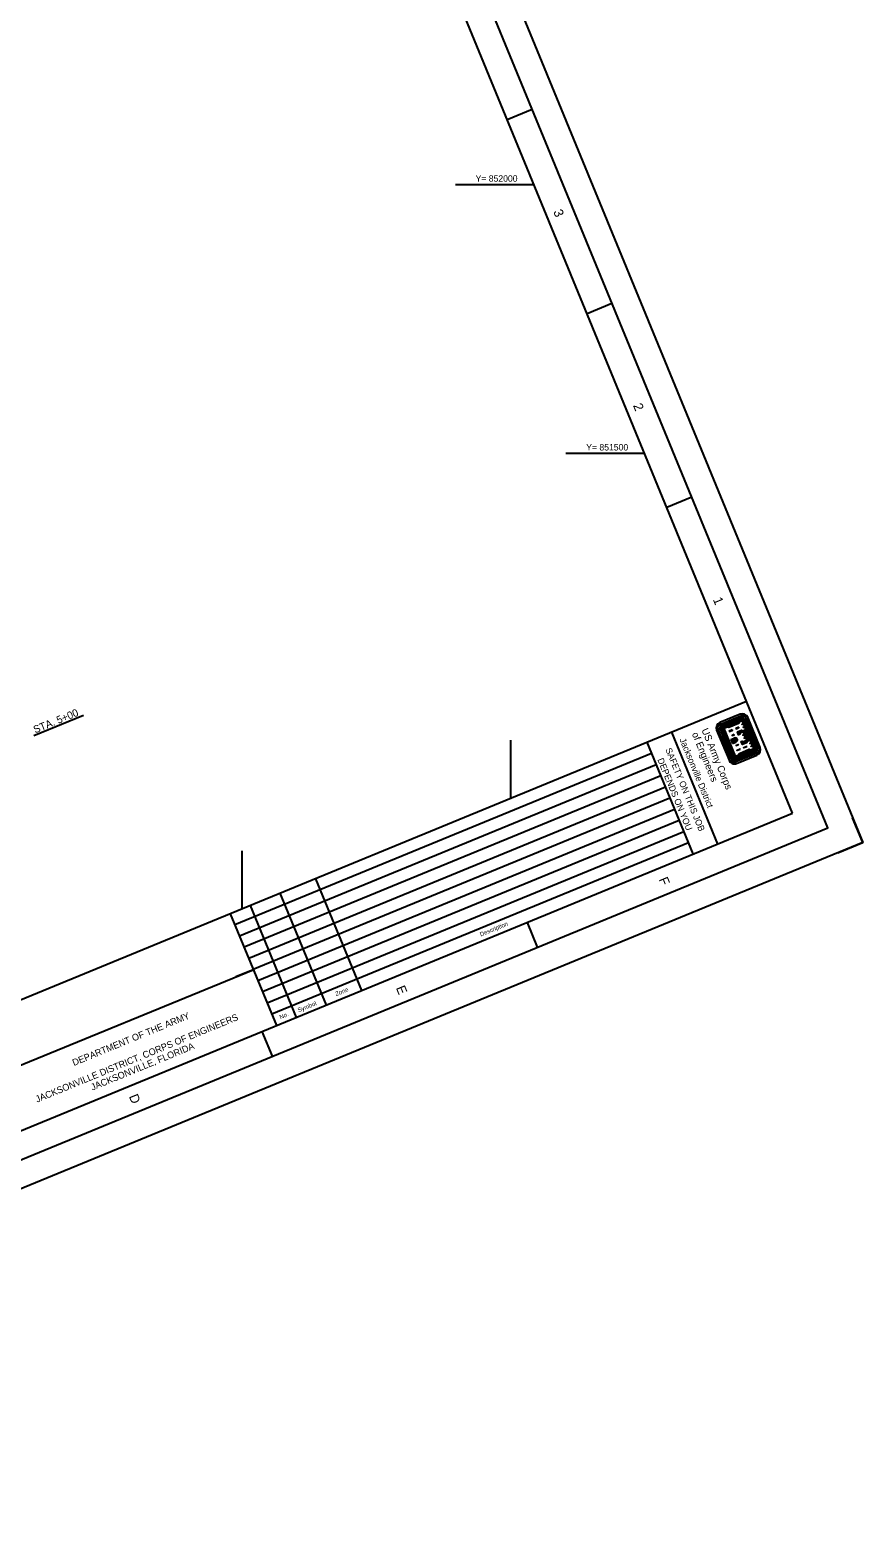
# Model space of a CAD drawing. Extents: x 580836 to 585655, y 849482 to 854845.
# Drawn here: x 584106 to 585655, y 849482 to 852287 of the extents above; entities that cross this region are included whole.
import ezdxf

# ---------------------------------------------------------------- set-up
doc = ezdxf.new("R2010")
doc.units = 0
for name, color, linetype in [('G-ANNO-NPLT', 7, 'Continuous'), ('G-ANNO-TEXT-LOGO', 7, 'Continuous'), ('G-ANNO-TEXT-TTLB', 7, 'Continuous'), ('G-ANNO-TTLB', 7, 'Continuous'), ('V-ALGN-TEXT', 7, 'Continuous'), ('V-TOPO-COOR-STAT', 7, 'Continuous')]:
    doc.layers.add(name, color=color, linetype=linetype)

msp = doc.modelspace()

# ---------------------------------------------------------------- linework, layer by layer
at = {"layer": 'G-ANNO-NPLT'}
msp.add_lwpolyline([(583980.5, 854844.8), (585654.5, 850775.7), (582510.3, 849482.1), (580836.2, 853551.2)], close=True, dxfattribs=at)
msp.add_lwpolyline([(585608.3, 850756.7), (585654.5, 850775.7), (585635.5, 850821.9)], dxfattribs=at)
at = {"layer": 'G-ANNO-TEXT-LOGO'}
for p, q in [((585426.4, 851014.5), (585388.5, 850998.9)), ((585382.6, 850984.9), (585405.7, 850928.7)), ((585408.8, 850929.9), (585385.7, 850986.2)), ((585412, 850931.3), (585388.9, 850987.5)), ((585412.8, 850931.6), (585389.6, 850987.8)), ((585389.7, 850995.9), (585427.6, 851011.5)), ((585413.6, 850931.9), (585390.5, 850988.1)), ((585429, 851008.3), (585391.1, 850992.7)), ((585414.4, 850932.3), (585391.3, 850988.5)), ((585429.3, 851007.5), (585391.4, 850991.9)), ((585429.6, 851006.7), (585391.7, 850991.1)), ((585415.2, 850932.6), (585392, 850988.8)), ((585430, 851005.9), (585392.1, 850990.3)), ((585430.3, 851005.1), (585392.4, 850989.5)), ((585430.7, 851004.2), (585393, 850988.8)), ((585415.8, 850933.3), (585393, 850988.8)), ((585431, 851003.5), (585394.2, 850988.4)), ((585416.4, 850934.3), (585394.2, 850988.4)), ((585423.2, 850999.5), (585403.8, 850991.6)), ((585422.7, 850998.4), (585405, 850991.1)), ((585454.2, 850948.6), (585431.1, 851004.8)), ((585455, 850949), (585431.9, 851005.2)), ((585455.8, 850949.3), (585432.6, 851005.5)), ((585456.6, 850949.6), (585433.5, 851005.8)), ((585457.4, 850949.9), (585434.3, 851006.2)), ((585437.4, 851007.5), (585460.6, 850951.2)), ((585438.3, 850985), (585445.4, 850967.8)), ((585463.5, 850952.5), (585440.4, 851008.7)), ((585409.2, 850967.3), (585415.4, 850969.8)), ((585409.2, 850967.3), (585412.2, 850959.9)), ((585409.5, 850966.6), (585415.7, 850969.1)), ((585409.8, 850965.7), (585416, 850968.3)), ((585410.2, 850964.9), (585416.4, 850967.4)), ((585410.5, 850964.2), (585416.7, 850966.7)), ((585410.9, 850963), (585417.1, 850965.6)), ((585411.3, 850962.3), (585417.4, 850964.9)), ((585411.6, 850961.5), (585417.8, 850964)), ((585411.9, 850960.6), (585418.1, 850963.2)), ((585412.2, 850959.9), (585418.4, 850962.4)), ((585433.5, 850983), (585440.6, 850965.8)), ((585434.4, 850983.4), (585441.4, 850966.2)), ((585435.1, 850983.7), (585442.2, 850966.5)), ((585435.9, 850984), (585443, 850966.8)), ((585436.8, 850984.4), (585443.8, 850967.2)), ((585437.5, 850984.7), (585444.6, 850967.5)), ((585453.5, 850948.8), (585415.8, 850933.3)), ((585453.8, 850947.9), (585415.9, 850932.3)), ((585454.2, 850947.1), (585416.3, 850931.5)), ((585453.2, 850949.5), (585416.4, 850934.3)), ((585454.5, 850946.3), (585416.6, 850930.7)), ((585454.8, 850945.5), (585416.9, 850929.9)), ((585455.2, 850944.7), (585417.2, 850929.1)), ((585456.5, 850941.5), (585418.5, 850925.9)), ((585419.8, 850922.9), (585457.7, 850938.5)), ((585444.8, 850946.8), (585425.5, 850938.9)), ((585443.7, 850947.3), (585426, 850940.1))]:
    msp.add_line(p, q, dxfattribs=at)
for points in [[(585431.2, 851002.9), (585423.9, 850999.8), (585423, 850997.6), (585405.3, 850990.4), (585403, 850991.2), (585395, 850987.9), (585416.7, 850935.2), (585424.7, 850938.5), (585425.7, 850940.9), (585443.3, 850948.2), (585445.6, 850947.1), (585452.9, 850950.1), (585450.1, 850957.1), (585447.9, 850962.4), (585445.8, 850967.4), (585438.5, 850964.4), (585437.6, 850962), (585431.2, 850959.4), (585429.6, 850963.2), (585430.2, 850963.5), (585432.6, 850962.5), (585439.8, 850965.5), (585436.9, 850972.4), (585434.7, 850977.8), (585432.7, 850982.7), (585425.5, 850979.7), (585424.5, 850977.4), (585423.9, 850977.1), (585422.3, 850981), (585428.7, 850983.7), (585431, 850982.6), (585438.3, 850985.7), (585435.4, 850992.6), (585433.2, 850998), (585431.2, 851002.9)], [(585430.7, 851001.8), (585424.6, 850999.3), (585423.6, 850996.9), (585405.3, 850989.4), (585403, 850990.4), (585396.1, 850987.5), (585417.2, 850936.3), (585424, 850939.1), (585425, 850941.6), (585443.3, 850949.1), (585445.7, 850948), (585451.8, 850950.5), (585449.7, 850955.5), (585446.9, 850954.4), (585446.7, 850954.8), (585449.5, 850956), (585447.5, 850960.9), (585444.6, 850959.7), (585444.5, 850960.1), (585447.4, 850961.3), (585445.3, 850966.3), (585439.2, 850963.7), (585438.2, 850961.4), (585430.7, 850958.3), (585428.5, 850963.7), (585430.3, 850964.4), (585432.6, 850963.4), (585438.7, 850965.9), (585436.7, 850970.9), (585433.8, 850969.7), (585433.7, 850970.1), (585436.5, 850971.3), (585434.5, 850976.3), (585431.6, 850975.1), (585431.4, 850975.6), (585434.3, 850976.8), (585432.3, 850981.7), (585426.2, 850979.1), (585425.2, 850976.8), (585423.4, 850976.1), (585421.2, 850981.4), (585428.7, 850984.5), (585431.1, 850983.5), (585437.2, 850986), (585435.1, 850991), (585432.3, 850989.8), (585432.1, 850990.2), (585435, 850991.4), (585432.9, 850996.4), (585430, 850995.2), (585429.9, 850995.6), (585432.8, 850996.8), (585430.7, 851001.8)], [(585411.6, 850985.1), (585406.2, 850982.8), (585406.4, 850982.3), (585411.9, 850984.5), (585411.6, 850985.1)], [(585423.9, 850990.1), (585418.6, 850987.9), (585418.8, 850987.4), (585424.2, 850989.6), (585423.9, 850990.1)], [(585415.1, 850976.5), (585411.3, 850975), (585411.5, 850974.5), (585415.3, 850976.1), (585415.1, 850976.5)], [(585423, 850957.5), (585419.2, 850955.9), (585419, 850956.4), (585422.8, 850958), (585423, 850957.5)], [(585429.4, 850982.4), (585428.7, 850982.7), (585423.4, 850980.5), (585424.2, 850978.8), (585424.9, 850980.5), (585429.5, 850982.4)], [(585437.2, 850963.4), (585436.9, 850962.7), (585431.7, 850960.5), (585431, 850962.2), (585432.6, 850961.6), (585437.3, 850963.5)], [(585426.4, 850949.1), (585421, 850946.8), (585420.8, 850947.3), (585426.2, 850949.5), (585426.4, 850949.1)], [(585438.7, 850954.1), (585433.4, 850951.9), (585433.2, 850952.4), (585438.5, 850954.6), (585438.7, 850954.1)]]:
    msp.add_lwpolyline(points, dxfattribs=at)
for centre, major_axis, start_param, end_param in [((585430.5, 851004.6), (4.08, -9.91), 1.57078, 3.141576), ((585430.5, 851004.6), (2.85, -6.93), 1.57078, 3.141576), ((585392.6, 850989), (-4.08, 9.91), 6.28317, 7.853966), ((585392.6, 850989), (-2.85, 6.93), 6.28317, 7.853966), ((585392.6, 850989), (-1.53, 3.72), 6.28317, 7.853966), ((585392.6, 850989), (-1.2, 2.91), 6.28317, 7.853966), ((585392.6, 850989), (-0.87, 2.11), 6.28317, 7.853966), ((585392.6, 850989), (-0.54, 1.31), 6.28317, 7.853966), ((585392.6, 850989), (-0.208, 0.505), 6.28317, 7.853966), ((585430.5, 851004.6), (1.53, -3.72), 1.57078, 3.141576), ((585430.5, 851004.6), (1.2, -2.91), 1.57078, 3.141576), ((585430.5, 851004.6), (0.87, -2.11), 1.57078, 3.141576), ((585430.5, 851004.6), (0.54, -1.31), 1.57078, 3.141576), ((585430.5, 851004.6), (0.208, -0.505), 1.57078, 3.141576), ((585417.1, 850964.6), (-2.11, 5.14), 4.985832, 6.214359), ((585417.1, 850964.6), (-1.78, 4.33), 4.947465, 6.21436), ((585417.1, 850964.6), (-1.45, 3.53), 4.947465, 6.21436), ((585417.1, 850964.6), (-1.12, 2.73), 4.947465, 6.21436), ((585417.1, 850964.6), (-0.79, 1.92), 4.947465, 6.214359), ((585415.9, 850967.4), (0.79, -1.92), 0.068794, 1.335689), ((585415.9, 850967.4), (1.12, -2.73), 0.068794, 1.335689), ((585415.9, 850967.4), (1.45, -3.53), 0.068795, 1.335689), ((585415.9, 850967.4), (1.78, -4.33), 0.068795, 1.335689), ((585415.9, 850967.4), (2.11, -5.14), 0.068795, 1.29842), ((585415.7, 850932.8), (4.08, -9.91), 4.712373, 6.28317), ((585415.7, 850932.8), (-2.85, 6.93), 1.570781, 3.141577), ((585415.7, 850932.8), (1.53, -3.72), 4.712373, 6.28317), ((585415.7, 850932.8), (1.2, -2.91), 4.712373, 6.28317), ((585415.7, 850932.8), (0.87, -2.11), 4.712373, 6.28317), ((585415.7, 850932.8), (0.54, -1.31), 4.712373, 6.28317), ((585415.7, 850932.8), (0.208, -0.505), 4.712373, 6.28317), ((585453.6, 850948.4), (0.208, -0.505), 6.283169, 7.853965), ((585453.6, 850948.4), (0.54, -1.31), 6.283169, 7.853965), ((585453.6, 850948.4), (0.87, -2.11), 6.283169, 7.853965), ((585453.6, 850948.4), (1.2, -2.91), 6.283169, 7.853965), ((585453.6, 850948.4), (1.53, -3.72), 6.283169, 7.853965), ((585453.6, 850948.4), (2.85, -6.93), 6.28317, 7.853966), ((585453.6, 850948.4), (4.08, -9.91), 6.283169, 7.853965)]:
    msp.add_ellipse(centre, major_axis=major_axis, ratio=0.99964, start_param=start_param, end_param=end_param, dxfattribs=at)
at = {"layer": 'G-ANNO-TTLB'}
for p, q in [((585039.5, 852139.2), (584993.3, 852120.2)), ((585187.9, 851778.6), (585141.6, 851759.5)), ((585336.3, 851417.9), (585290, 851398.9)), ((585438.4, 851038.2), (582479.1, 849820.7)), ((585252.9, 850962.5), (585338.5, 850754.5)), ((585298.5, 850980.7), (585384.2, 850772.6)), ((585261.6, 850941.3), (584486.7, 850622.5)), ((585270.2, 850920.5), (584495.3, 850601.7)), ((585278.7, 850899.7), (584503.8, 850580.9)), ((585287.3, 850878.9), (584512.4, 850560.1)), ((585295.8, 850858.1), (584521, 850539.3)), ((585304.4, 850837.3), (584529.5, 850518.5)), ((585313, 850816.5), (584538.1, 850497.7)), ((585321.5, 850795.7), (584546.6, 850476.9)), ((585330.1, 850774.9), (584555.2, 850456.1)), ((584636.4, 850708.2), (584722, 850500.2)), ((584570.6, 850681.2), (584656.2, 850473.1)), ((584515.1, 850658.3), (584600.6, 850450.2)), ((584478.2, 850643.2), (584563.8, 850435.1)), ((585049.7, 850580.9), (585030.6, 850627.1)), ((583725.9, 850212.7), (584521, 850539.1)), ((584521, 850539.1), (584488.3, 850525.7)), ((584556.5, 850378), (584537.4, 850424.2))]:
    msp.add_line(p, q, dxfattribs=at)
for points in [[(580901.5, 853523.9), (582537.5, 849547.4), (585589.3, 850802.9), (583953.2, 854779.5)], [(585524, 850830.1), (583954.6, 854644.9), (580995.3, 853427.4), (582564.7, 849612.6)]]:
    msp.add_lwpolyline(points, close=True, dxfattribs=at)
at = {"layer": 'V-ALGN-TEXT'}
msp.add_line((584113, 850974.5), (584205.4, 851012.6), dxfattribs=at)
at = {"layer": 'V-TOPO-COOR-STAT'}
for p, q in [((584896.7, 852000), (585042.7, 852000)), ((585102.4, 851500), (585248.4, 851500)), ((585000, 850857.9), (585000, 850966)), ((584500, 850652.2), (584500, 850760.3))]:
    msp.add_line(p, q, dxfattribs=at)

# ---------------------------------------------------------------- texts
at = {"layer": 'G-ANNO-TEXT-TTLB'}
for s, height, rotation, p in [('US Army Corps', 13.086, 292.363, (585354.2, 850985.2)), ('Jacksonville District', 11.9, 292.363, (585313.3, 850967.3)), ('of Engineers', 13.086, 292.363, (585336.3, 850977.9)), ('DEPENDS ON YOU', 11.9, 292.363, (585272.1, 850929.9)), ('SAFETY ON THIS JOB', 11.9, 292.363, (585287, 850948.8)), ('Description', 8, 22.363, (584944.2, 850600.6)), ('Symbol', 8, 22.363, (584605.3, 850459.6)), ('Zone', 8, 22.363, (584675.4, 850489.8)), ('JACKSONVILLE DISTRICT, CORPS OF ENGINEERS', 12.5, 22.363, (584118.8, 850291.6)), ('DEPARTMENT OF THE ARMY', 12.5, 22.363, (584187.4, 850359.8)), ('No.', 8, 22.363, (584571.5, 850446.8)), ('JACKSONVILLE, FLORIDA', 12.5, 22.363, (584221.8, 850314))]:
    msp.add_text(s, height=height, rotation=rotation, dxfattribs=at).set_placement(p)
at = {"layer": 'G-ANNO-TTLB'}
for s, p in [('3', (585078.5, 851949.4)), ('2', (585226.9, 851588.7)), ('1', (585375.3, 851228.1)), ('F', (585274.7, 850707.2)), ('E', (584785.9, 850505.3)), ('D', (584289.3, 850303.4))]:
    msp.add_text(s, height=17.5, rotation=292.363, dxfattribs=at).set_placement(p)
at = {"layer": 'V-ALGN-TEXT'}
msp.add_text('STA. 5+00', height=13.92, rotation=22.363, dxfattribs=at).set_placement((584115.3, 850978.5))
at = {"layer": 'V-TOPO-COOR-STAT'}
for s, p in [('Y= 852000', (584934.3, 852005)), ('Y= 851500', (585140.1, 851505))]:
    msp.add_text(s, height=12, dxfattribs=at).set_placement(p)

doc.saveas('drawing.dxf')
